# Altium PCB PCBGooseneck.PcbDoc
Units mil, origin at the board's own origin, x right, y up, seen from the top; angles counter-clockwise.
Board outline 3535 x 2275 mil, 2 copper layers (Top Layer, Bottom Layer); 26 components, 20 nets, 64 pads, 1 vias.
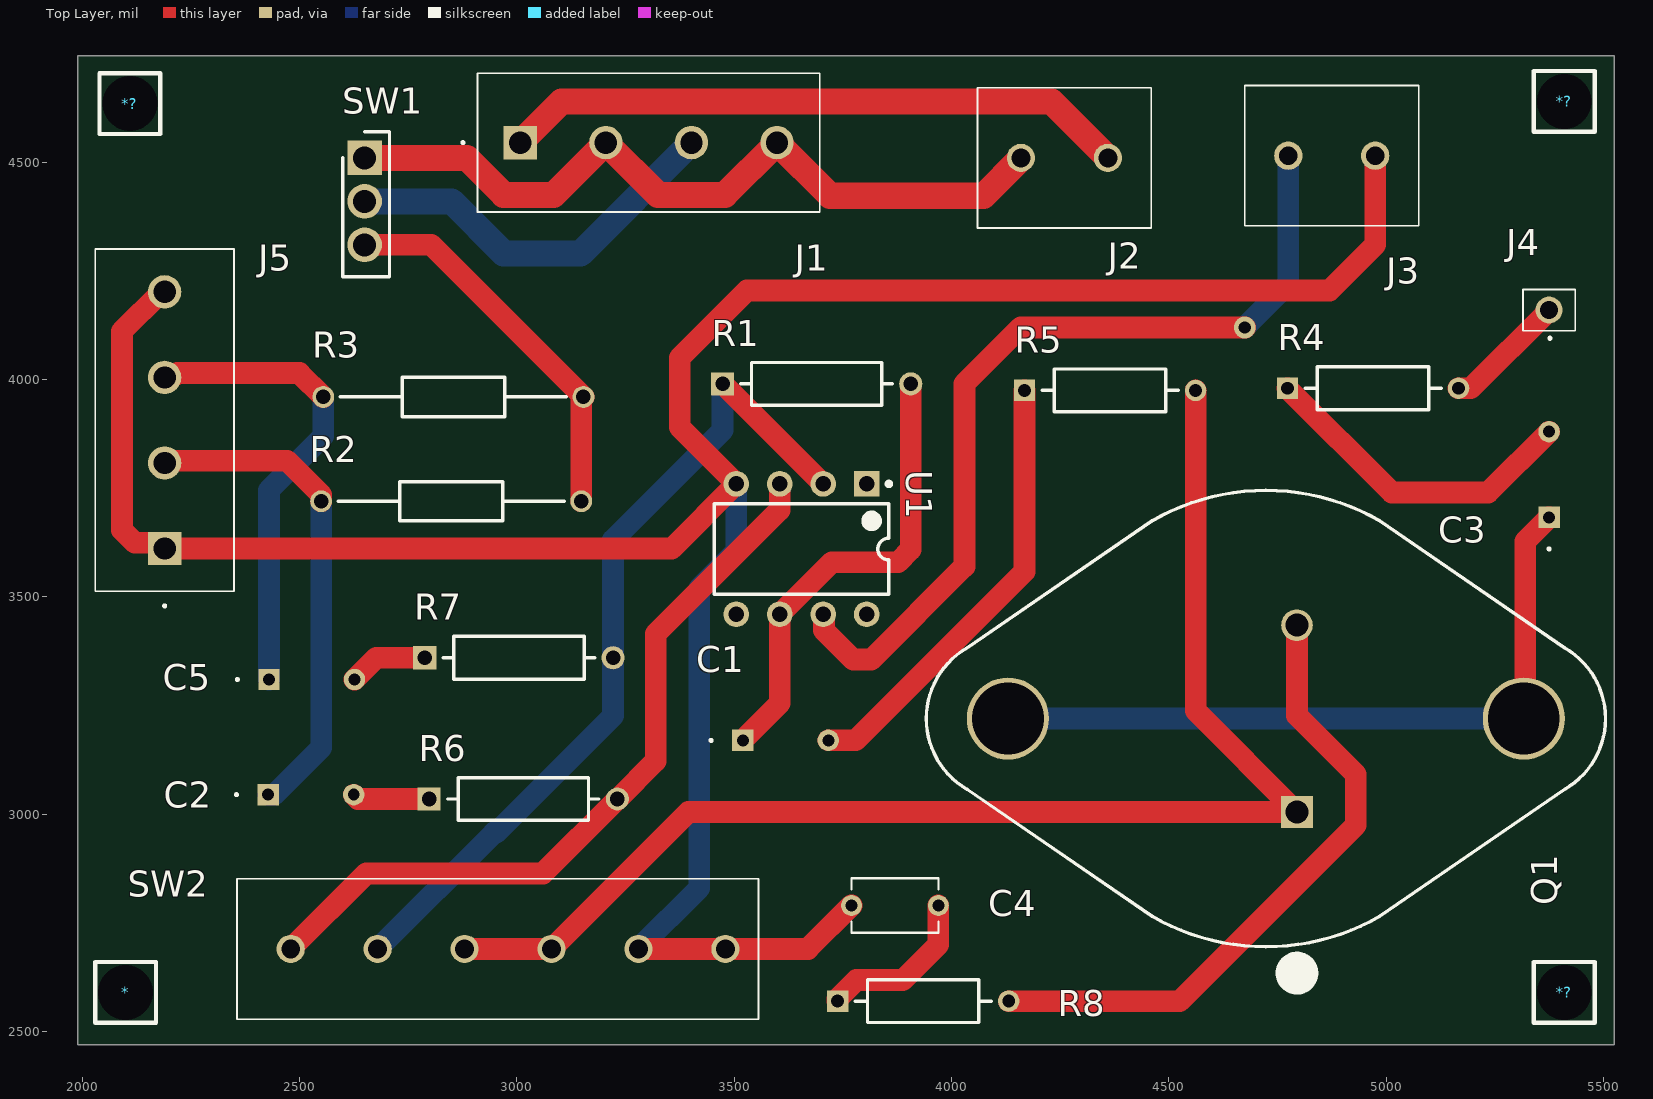
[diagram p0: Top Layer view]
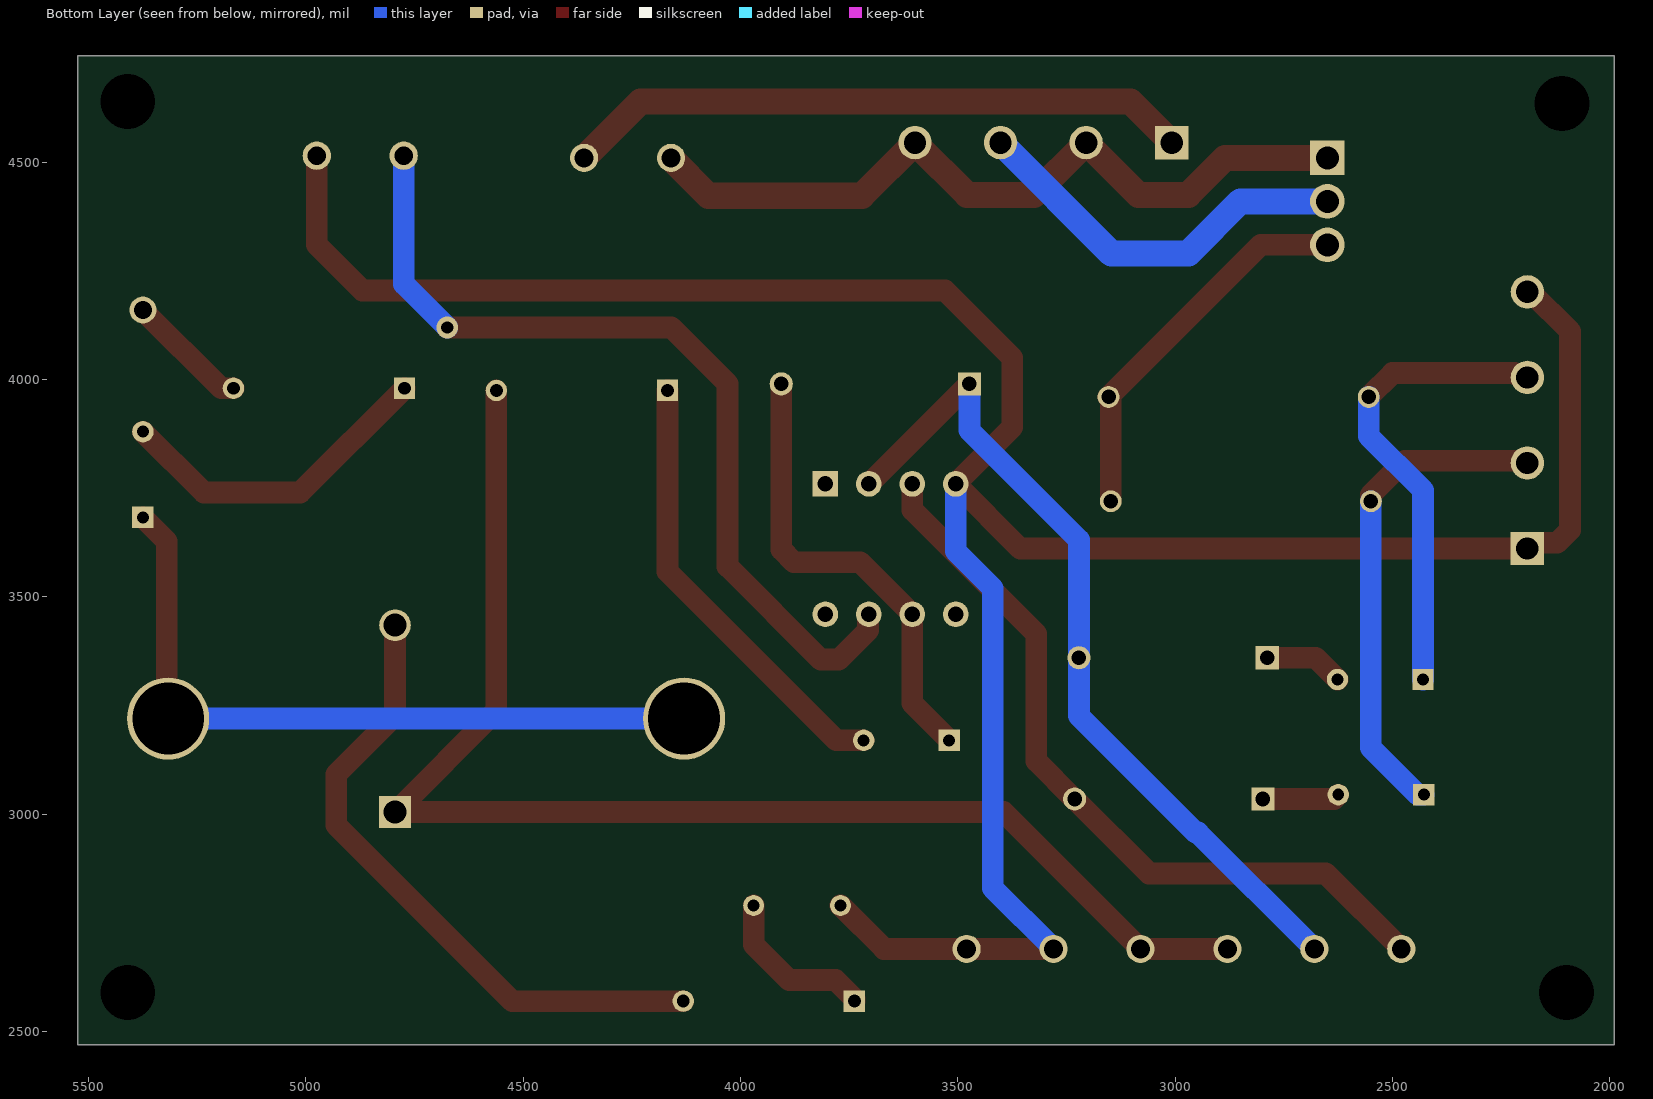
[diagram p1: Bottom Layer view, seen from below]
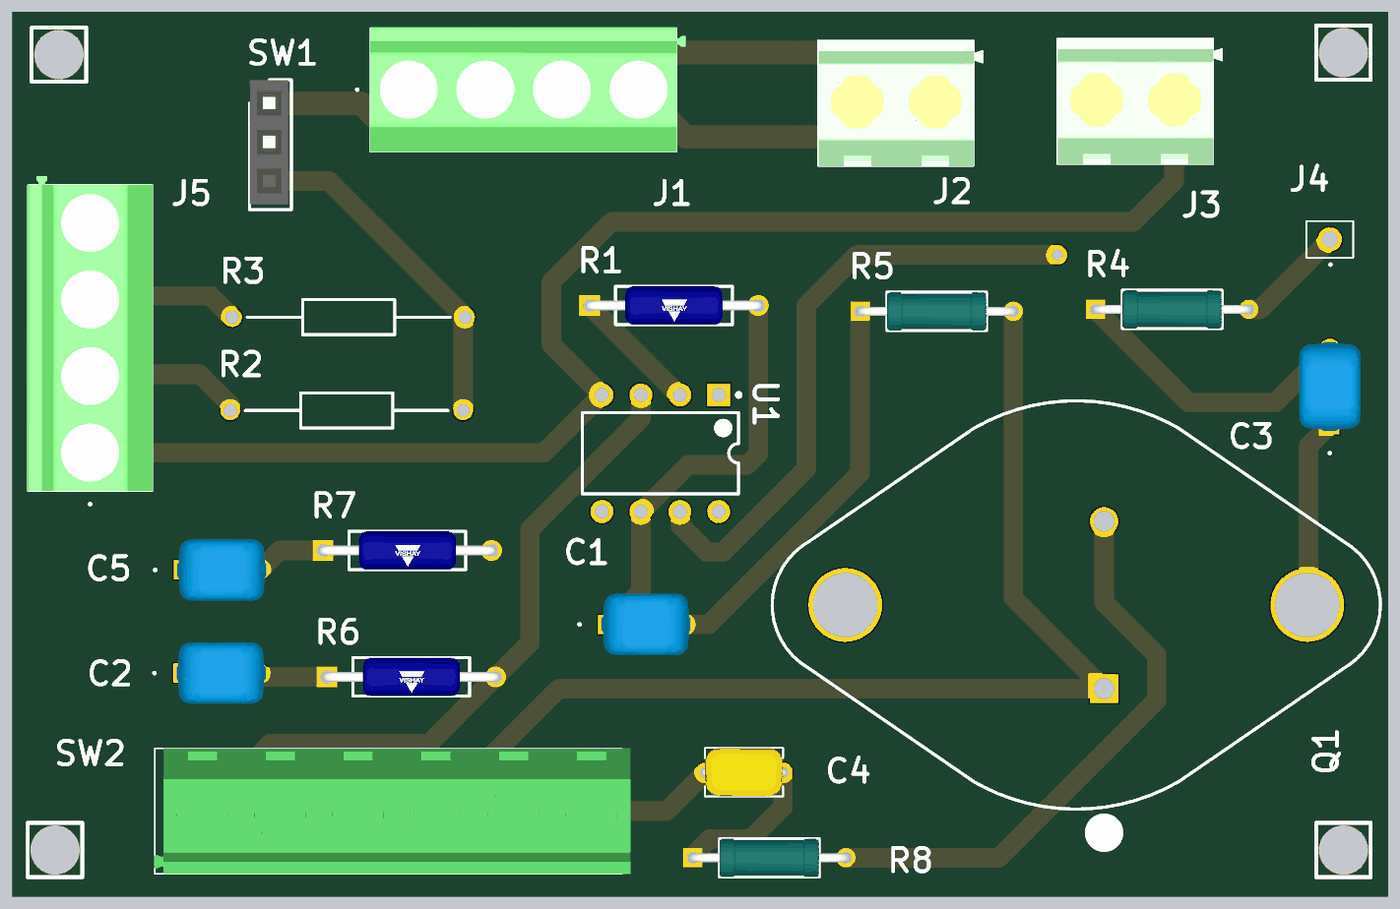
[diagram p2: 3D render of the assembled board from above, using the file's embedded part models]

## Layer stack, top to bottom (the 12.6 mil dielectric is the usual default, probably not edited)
Top Solder: solder mask 0.4, Solder Resist, Dk 3.5
Top Layer: signal copper 1.4
Dielectric 1: dielectric 12.6, FR-4, Dk 4.8
Bottom Layer: signal copper 1.4
Bottom Solder: solder mask 0.4, Solder Resist, Dk 3.5

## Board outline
1990,2470 5525,2470 5525,4745 1990,4745

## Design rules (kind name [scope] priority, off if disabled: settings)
Clearance [All] p1: gap=10 ignorepadtopadclearanceinfootprint=FALSE
PolygonConnect [All] p1: connectstyle=Relief reliefconductorwidth=10 reliefentries=4 polygonreliefangle="90 Angle" airgapwidth=10
RoutingVias [All] p1: holewidth=28 width=50 viastyle="Through Hole" minholewidth=28 minwidth=50 maxholewidth=28 maxwidth=50
SolderMaskExpansion [All] p1: expansion=4 istentingtop=FALSE
SupplyNets "Schematic Supply Nets_1" [InNet('GND')] p1: voltage=0.000
Width [All] p1: maxlimit=60 minlimit=20 preferedwidth=30
30 further rules are at their usual default settings.

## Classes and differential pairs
component class "Gooseneck Mic": * *? C1 C2 C3 C4 C5 J1 J2 J3 J4 J5 Q1 R1 R2 R3 R4 R5 R6 R7 R8 SW1 SW2 U1

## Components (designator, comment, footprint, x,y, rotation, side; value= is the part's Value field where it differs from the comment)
* "Mounting Hole" MTHNP3P2MM 2100,2590 r0 top
*? "Mounting Hole" MTHNP3P2MM 2110,4635 r0 top
*? "Mounting Hole" MTHNP3P2MM 5410,4640 r0 top
*? "Mounting Hole" MTHNP3P2MM 5410,2590 r0 top
C1 "10uF" FG20 3520,3170 r0 top
C2 "10uF" FG20 2428.15,3045 r0 top
C3 "10uF" FG20 5375,3683.15 r90 top
C4 "100nF" CAPRR508W50L508T317H508 3870,2790 r0 top value="0.10 µF"
C5 "10uF" FG20 2430,3310 r0 top
J1 "48V Boost Converter" 1729034 3008.15,4545 r0 top
J2 "9V Battery Screw Terminal" 2828372 4160,4510 r0 top
J3 "5V Supply" 2828372 4775,4515 r0 top
J4 "SSW-101-01-T-S" SSW-101-XX-YYY-S 5375,4160 r0 top
J5 "1729034_1" 1729034 2190,3611.3 r90 top
Q1 "2N3055G" ONSC-TO-204-3-1-07 4723.54,3220.04 r180 top
R1 "10k" FP-RLR07-MFG 3690,3990 r0 top
R2 "CF14JT6K80_1" RESAD1520W63L600D230 2550,3720 r0 top
R3 "CF14JT6K80_1" RESAD1520W63L600D230 2555,3960 r0 top
R4 "100" FP-MRS25-MFG 4970,3980 r0 top
R5 "1k" FP-MRS25-MFG 4365,3975 r0 top
R6 "10k" FP-RLR07-MFG 3015,3035 r0 top
R7 "10k" FP-RLR07-MFG 3005,3360 r0 top
R8 "1k" FP-MRS25-MFG 3935,2570 r0 top
SW1 "PPTC031LFBN-RC" RHDR3W80P0X254_1X3_812X254X850P 2650,4510 r270 top
SW2 "282837-6" 2828376 2480,2690 r0 top
U1 "LM741CN/NOPB" P0008A 3655,3610 r270 top

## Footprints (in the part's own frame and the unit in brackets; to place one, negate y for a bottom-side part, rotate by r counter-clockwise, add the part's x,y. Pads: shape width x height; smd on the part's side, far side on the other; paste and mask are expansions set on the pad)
1729034 [mm]
  rect 1.95x1.95 hole 1.3: 1(0,0)
  round 1.95 hole 1.3: 2(5,0) 3(10,0) 4(15,0)
  silkscreen extent -3.4,-4.05 17.5,4.05, body extent -2.49,-4.08 18.08,4.07, height 10.51
2828372 [mm]
  round 1.65 hole 1.1: 1(0,0) 2(5.08,0)
  silkscreen extent -2.54,-4.1 7.62,4.1, body extent -2.51,-4.11 8.25,4.09, height 9.84
2828376 [mm]
  round 1.65 hole 1.1: 1(0,0) 2(5.08,0) 3(10.16,0) 4(15.24,0) 5(20.32,0) 6(25.4,0)
  silkscreen extent -3.14,-4.1 27.34,4.1, body extent -3.18,-4.1 27.9,4.1, height 10.61
CAPRR508W50L508T317H508 [mm]
  round 1.218 hole 0.71: 1(-2.54,0) 2(2.54,0)
  silkscreen extent -2.54,-1.59 2.54,1.59, body extent -2.79,-1.59 2.79,1.59, height 5.86
FG20 [mm]
  rect 1.25x1.25 hole 0.7: 1(0,0)
  round 1.25 hole 0.7: 2(5,0)
  silkscreen extent -1.9,-0.05 -1.8,0.05, body extent -0.4,-2 5.4,2, height 7.25
FP-MRS25-MFG [mm]
  rect 1.25x1.25 hole 0.75 paste-2539.97 mask+0: 1(-5,0)
  round 1.25 hole 0.75 paste-2539.97 mask+0: 2(5,0)
  silkscreen extent -3.98,-1.25 3.98,1.25, body extent -5.72,-1.35 5.72,1.35, height 0.25
FP-RLR07-MFG [mm]
  rect 1.35x1.35 hole 0.85 paste-2539.97 mask+0: 1(-5.5,0)
  round 1.35 hole 0.85 paste-2539.97 mask+0: 2(5.5,0)
  silkscreen extent -4.43,-1.25 4.43,1.25, body extent -6.27,-1.35 6.27,1.35, height 0.25
MTHNP3P2MM [mm] "Mounting Hole Non-Plated 3.2mm"
  round 0 hole 3.2: ""(0,0)
  silkscreen extent -1.78,-1.78 1.78,1.78
ONSC-TO-204-3-1-07 [mm] "TO-204, Pin Spacing 10.92mm, Lead Dia. 1.09 mm (max)"
  rect 1.85x1.85 hole 1.35: 1(-1.815,5.46)
  round 1.85 hole 1.35: 2(-1.815,-5.46)
  round 4.8 hole 4.19 mask+0.102: 3(-15.075,0) 4(15.075,0)
  silkscreen extent -19.85,-13.33 19.85,15.5, body extent -19.84,-13.33 19.84,13.33, height 8.51
P0008A [mm] "DIP, 8-Leads, Body 10.15x6.6mm, Pitch 2.54mm"
  rect 1.5x1.5 hole 0.9: 1(-3.81,3.81)
  round 1.5 hole 0.9: 2(-3.81,1.27) 3(-3.81,-1.27) 4(-3.81,-3.81) 5(3.81,-3.81) 6(3.81,-1.27) 7(3.81,1.27) 8(3.81,3.81)
  silkscreen extent -3.93,-5.1 2.65,5.24, body extent -3.95,-5.07 3.95,5.07, height 5.08
RESAD1520W63L600D230 [mm]
  round 1.275 hole 0.85: 1(0,0) 2(15.2,0)
  silkscreen extent 0.99,-1.15 14.21,1.15
RHDR3W80P0X254_1X3_812X254X850P [mm]
  rect 2.025x2.025 hole 1.35: 1(0,0)
  round 2.025 hole 1.35: 2(2.54,0) 3(5.08,0)
  silkscreen extent -1.52,-1.27 6.95,1.46, body extent -1.52,-1.27 6.6,1.27, height 8.5
SSW-101-XX-YYY-S [mm]
  round 1.57 hole 1.04: 1(0,0)
  silkscreen extent -1.53,-1.7 1.53,1.2

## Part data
C1 C2 C3 C5: library part FG20X7R1H106KRT06, "Capacitor FG20X7R1H106KRT06", Manufacturer_Name=TDK, Mouser Part Number=810-FG20X7R1H106KRT6
C4: library part b4654b650e69147ec39a6b967a45e02, "CAP CER 0.1UF 50V X7R 0805 C0805C104K5RACTU High Frequency Noise Filtering", Capacitance="0.10 μF", Manufacturer=KEMET, Manufacturer Part Number=C0805C104K5RACTU, Package=C0805C-DN, Temperature="-55°C to +125°C", Temperature Characteristic=X7R, Temperature Coefficient=30ppm/°C, Temperature Range High=+125°C, Temperature Range Low=-55°C, Tolerance=0.1, Voltage Rating="50 V"
J1: library part 1729034_1, "Connector 1729034_1", Arrow Part Number=1729034, Manufacturer_Name="Phoenix Contact", Mouser Part Number=651-1729034
J2 J3: library part 282837-2, "Connector 282837-2", Manufacturer_Name="TE Connectivity", Mouser Part Number=571-2828372
J4: "Connector", Manufacturer_Name=SAMTEC, Mouser Part Number=200-SSW10101TS
J5: "Connector", Arrow Part Number=1729034, Manufacturer_Name="Phoenix Contact", Mouser Part Number=651-1729034
Q1: library part CMP-1048-01043-1, "Complementary Silicon Power Transistor, 3-Pin TO-204, Pb-Free, Tray", Manufacturer="On Semiconductor"
R1 R6 R7: library part CMP-00030-39449004-1, "RLR07C1002FSB14 Fixed Resistor, Metal Film, 0.25W, 10000ohm, 250V, 1% +/-Tol, 100ppm/Cel, Through Hole Mount", Case/Package=Conformal, Max Operating Temperature=150°C, Max Power Dissipation=250mW, Min Operating Temperature=-65°C, Resistance=10kΩ, Temperature Coefficient=100ppm/°C, Tolerance=1%, Voltage Rating=250V
R2 R3: "Resistor", Arrow Part Number=CF14JT6K80, Manufacturer_Name="Stackpole Electronics"
R4: library part CMP-00030-42757237-1, "MRS25000C1000FRP00 Resistor, 100 Ohm, ± 1%, 600 mW, Axial Leaded, Metal Film (Thin Film), Professional", Case/Package=Axial, Max Operating Temperature=155°C, Max Power Dissipation=600mW, Min Operating Temperature=-55°C, Resistance=100Ω, Temperature Coefficient=50ppm/°C, Tolerance=1%, Voltage Rating=350V
R5 R8: library part CMP-02408-000051-1, "RES 1K OHM 0.6W 1% AXIAL", Case/Package=Axial, Max Operating Temperature=155°C, Max Power Dissipation=600mW, Min Operating Temperature=-55°C, Package Quantity=5000, Resistance=1kR, Resistance Tolerance=1%, Resistor Type="Metal Film", Temperature Coefficient=50ppm/°C, Voltage Rating=350V
SW1: "Connector", Manufacturer_Name=Sullins
SW2: "Connector", Manufacturer_Name="TE Connectivity", Mouser Part Number=571-2828376
U1: library part CMP-0055-00162-3, "Operational Amplifier, 8-pin MDIP, Pb-Free", Manufacturer="Texas Instruments", Package Reference=P0008A, PackageTopMarking=NSUZXYTTE#*LM*741CN, PowerWise=N

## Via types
v1: diameter 50, hole 28, Top Layer to Bottom Layer, 1 vias

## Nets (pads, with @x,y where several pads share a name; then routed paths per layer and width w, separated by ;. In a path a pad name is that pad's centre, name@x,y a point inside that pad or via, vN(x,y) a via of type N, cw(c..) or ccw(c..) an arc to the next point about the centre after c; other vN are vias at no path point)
GND: C4.1 J3.2 J5.1 J5.4 SW2.5 SW2.6 U1.4 | length 6036.7
  Top Layer w50: J5.4 2182.76,4201.85 2091.61,4110.71 2091.61,3653.97 2120.9,3624.69 2176.61,3624.69 J5.1 3356.3,3611.3 U1.4 3375,3890 3375,4050 3530,4205 4870,4205 4975,4310 J3.2 ; SW2.5 SW2.6 3670,2690 C4.1
  Bottom Layer w50: SW2.5 3420,2830 3420,3520 3505,3605 U1.4
NetC1_1: C1.1 R1.2 U1.6 | length 1069.3
  Top Layer w50: C1.1 3605,3255 U1.6 3725,3580 3877.25,3580 3906.54,3609.29 R1.2
NetC1_2: C1.2 R5.1 | length 1028.9
  Top Layer w50: C1.2 3780,3170 4168.15,3558.15 R5.1
NetC2_1: C2.1 J5.2 R2.1 | length 1143.3
  Top Layer w50: J5.2 2195.12,3813.27 2471.73,3813.27 2549.96,3735.04 R2.1 R2.1
  Bottom Layer w50: C2.1 2442.36,3045 2550,3152.64 R2.1
NetC2_2: C2.2 R6.1 | length 177.6
  Top Layer w50: C2.2 2635,3035 R6.1
NetC3_1: C3.1 Q1.3 Q1.4 | length 1674.1
  Top Layer w50: Q1.3 5320,3222.99 5320,3628.15 C3.1
  Bottom Layer w50: Q1.4 Q1.3
NetC3_2: C3.2 R4.1 | length 759.1
  Top Layer w50: R4.1 5012.96,3740.19 5235.19,3740.19 C3.2
NetC4_2: C4.2 R8.1 | length 378.6
  Top Layer w50: R8.1 3738.15,2575 3781.5,2618.35 3888.35,2618.35 3970,2700 C4.2
NetC5_1: C5.1 J5.3 R3.1 | length 1093.7
  Top Layer w50: J5.3 2195.12,4010.12 2214.05,4010.12 2218.93,4015 2499.95,4015 2554.95,3960 R3.1
  Bottom Layer w50: C5.1 2430,3745 2555,3870 R3.1
NetC5_2: C5.2 R7.1 | length 182.3
  Top Layer w50: C5.2 2676.85,3360 R7.1
NetJ1_1: J1.1 J2.2 | length 1445
  Top Layer w60: J1.1 3103.15,4640 4230,4640 J2.2
NetJ1_2: J1.2 J1.4 J2.1 SW1.1 | length 1777.3
  Top Layer w60: SW1.1 2885,4510 2970,4425 3085,4425 J1.2 3325,4425 3478.7,4425 J1.4@3595.49,4541.79 ; J1.4 3720.85,4422.86 4074.2,4422.86 4160,4508.66 J2.1
NetJ1_3: J1.3 SW1.2 | length 907.2
  Bottom Layer w60: SW1.2 2850,4410 2970,4290 3146.85,4290 J1.3
NetJ3_1: J3.1 U1.7 | length 2037.2
  Top Layer w50: U1.7 3706.73,3458.27 3706.73,3423.27 3774.29,3355.71 3815.71,3355.71 4030,3570 4030,3990 4160,4120 v1@4675.43,4120 ; J3.1 J3.1@4777.86,4517.86
  Bottom Layer w50: v1(4675,4120) 4775,4220 J3.1
NetJ4_1: J4.1 R4.2 | length 282.7
  Top Layer w50: R4.2 5195,3980 J4.1
NetQ1_1: Q1.1 R5.2 SW2.3 SW2.4 | length 3112
  Top Layer w50: SW2.3 SW2.4 3395.08,3005.08 Q1.1 4561.85,3238.23 R5.2
NetQ1_2: Q1.2 R8.2 | length 1481.8
  Top Layer w50: R8.2 4525,2570 4930,2975 4930,3092.2 4795,3227.2 Q1.2
NetR1_1: R1.1 R7.2 SW2.2 U1.2 | length 1958.4
  Top Layer w50: R1.1 3703.46,3760 U1.2
  Bottom Layer w50: SW2.2 2947.88,2957.88 2952.88,2957.88 3221.54,3226.54 R7.2 3221.54,3631.54 3473.46,3883.46 R1.1
NetR2_2: R2.2 R3.2 SW1.3 | length 890.5
  Top Layer w50: SW1.3 2803.43,4310 R3.2 3153.43,3959.95 3148.43,3954.95 R2.2
NetR6_2: R6.2 SW2.1 U1.3 | length 1774.6
  Top Layer w50: SW2.1 2653.63,2863.63 3060.17,2863.63 R6.2 3232.39,3035 3320,3122.61 3320,3415 3605,3700 U1.3
pads on no net: *. *?. U1.1 U1.5 U1.8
